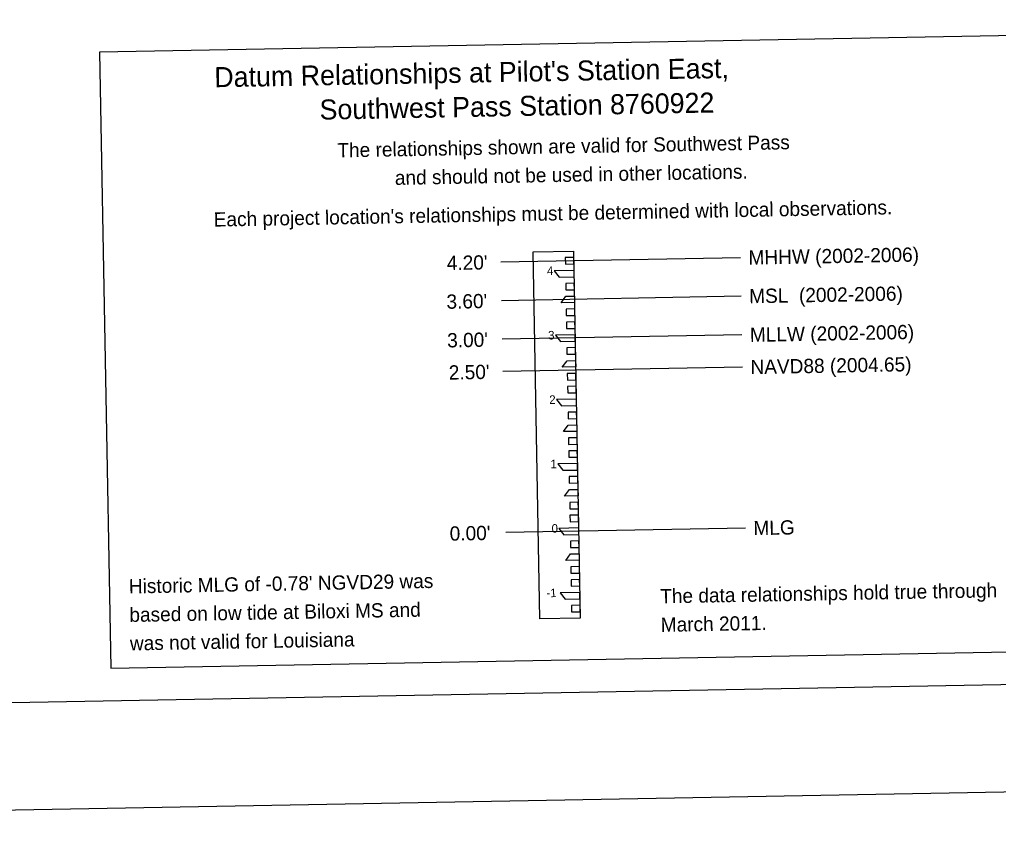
# Model space of a CAD drawing. Extents: x 3925854 to 3964121, y 224593 to 250589.
# Drawn here: x 3936067 to 3941766, y 225176 to 229943 of the extents above; entities that cross this region are included whole.
import ezdxf

# ---------------------------------------------------------------- set-up
doc = ezdxf.new("R2010")
doc.units = 0
for name, color, linetype in [('G-ANNO-NPLT', 7, 'Continuous'), ('V-ANNO-NOTE', 7, 'Continuous'), ('V-ANNO-SYMB', 7, 'Continuous')]:
    doc.layers.add(name, color=color, linetype=linetype)

msp = doc.modelspace()

# ---------------------------------------------------------------- linework, layer by layer
at = {"layer": 'G-ANNO-NPLT'}
msp.add_lwpolyline([(3926876.838, 225176.36), (3963537.445, 225842.962), (3963098.093, 250005.635), (3926437.486, 249339.033)], close=True, dxfattribs=at)
at = {"layer": 'V-ANNO-NOTE'}
for p, q in [((3940264.23, 228557.002), (3938869.243, 228531.637)), ((3940268.32, 228332.039), (3938873.334, 228306.674)), ((3940272.411, 228107.076), (3938877.424, 228081.711)), ((3940275.82, 227919.607), (3938880.833, 227894.242)), ((3940292.864, 226982.262), (3938897.877, 226956.897))]:
    msp.add_line(p, q, dxfattribs=at)
for points in [[(3936598.05, 226166.493), (3942365.934, 226271.371), (3942300.712, 229858.371), (3936532.827, 229753.493)], [(3939057.393, 228591.224), (3939293.152, 228595.511), (3939332.009, 226458.551), (3939096.249, 226454.264)], [(3939293.831, 228558.204), (3939244.066, 228557.299), (3939244.751, 228519.618), (3939294.516, 228520.523)], [(3939295.194, 228483.216), (3939180.065, 228481.123), (3939209.537, 228443.965), (3939295.879, 228445.535)], [(3939296.558, 228408.229), (3939246.793, 228407.324), (3939247.478, 228369.643), (3939297.243, 228370.548)], [(3939298.606, 228295.56), (3939220.054, 228294.132), (3939248.156, 228332.336), (3939297.921, 228333.241)], [(3939299.285, 228258.253), (3939249.52, 228257.349), (3939250.205, 228219.668), (3939299.97, 228220.573)], [(3939300.648, 228183.266), (3939250.883, 228182.361), (3939251.568, 228144.68), (3939301.333, 228145.585)], [(3939302.012, 228108.278), (3939186.882, 228106.185), (3939216.355, 228069.027), (3939302.697, 228070.597)], [(3939303.375, 228033.291), (3939253.61, 228032.386), (3939254.296, 227994.705), (3939304.06, 227995.61)], [(3939305.424, 227920.622), (3939226.872, 227919.194), (3939254.974, 227957.398), (3939304.739, 227958.303)], [(3939306.102, 227883.315), (3939256.337, 227882.411), (3939257.023, 227844.73), (3939306.787, 227845.635)], [(3939307.466, 227808.328), (3939257.701, 227807.423), (3939258.386, 227769.742), (3939308.151, 227770.647)], [(3939308.829, 227733.34), (3939193.7, 227731.247), (3939223.172, 227694.089), (3939309.514, 227695.659)], [(3939310.193, 227658.353), (3939260.428, 227657.448), (3939261.113, 227619.767), (3939310.878, 227620.672)], [(3939312.241, 227545.684), (3939233.689, 227544.256), (3939261.791, 227582.46), (3939311.556, 227583.365)], [(3939312.92, 227508.377), (3939263.155, 227507.473), (3939263.84, 227469.792), (3939313.605, 227470.697)], [(3939314.283, 227433.39), (3939264.518, 227432.485), (3939265.204, 227394.804), (3939314.968, 227395.709)], [(3939315.647, 227358.402), (3939200.517, 227356.309), (3939229.99, 227319.151), (3939316.332, 227320.721)], [(3939317.01, 227283.415), (3939267.245, 227282.51), (3939267.931, 227244.829), (3939317.695, 227245.734)], [(3939319.059, 227170.746), (3939240.507, 227169.318), (3939268.609, 227207.522), (3939318.374, 227208.427)], [(3939319.737, 227133.439), (3939269.972, 227132.534), (3939270.658, 227094.854), (3939320.422, 227095.759)], [(3939321.101, 227058.452), (3939271.336, 227057.547), (3939272.021, 227019.866), (3939321.786, 227020.771)], [(3939322.464, 226983.464), (3939207.335, 226981.371), (3939236.807, 226944.213), (3939323.149, 226945.783)], [(3939323.828, 226908.477), (3939274.063, 226907.572), (3939274.748, 226869.891), (3939324.513, 226870.796)], [(3939325.876, 226795.808), (3939247.324, 226794.38), (3939275.426, 226832.584), (3939325.191, 226833.489)], [(3939326.555, 226758.501), (3939276.79, 226757.596), (3939277.475, 226719.916), (3939327.24, 226720.821)], [(3939327.918, 226683.514), (3939278.153, 226682.609), (3939278.839, 226644.928), (3939328.603, 226645.833)], [(3939329.282, 226608.526), (3939214.152, 226606.433), (3939243.625, 226569.275), (3939329.967, 226570.845)], [(3939330.645, 226533.539), (3939280.88, 226532.634), (3939281.566, 226494.953), (3939331.33, 226495.858)]]:
    msp.add_lwpolyline(points, close=True, dxfattribs=at)
at = {"layer": 'V-ANNO-SYMB'}
msp.add_lwpolyline([(3929615.153, 225851.3), (3962692.886, 226452.755), (3962276.261, 249365.543), (3929198.528, 248764.088), (3929615.153, 225851.3)], dxfattribs=at)

# ---------------------------------------------------------------- texts
at = {"layer": 'V-ANNO-NOTE'}
for s, height, rotation, p in [("Datum Relationships at Pilot's Station East,", 116.7, 1.041707, (3937201.936, 229549.043)), ('Southwest Pass Station 8760922', 116.7, 1.041707, (3937814.695, 229360.452)), ('The relationships shown are valid for Southwest Pass', 83, 1.041699, (3937918.286, 229140.413)), ('and should not be used in other locations.', 83, 1.041699, (3938252.844, 228980.469)), ("Each project location's relationships must be determined with local observations.", 83, 1.041699, (3937198.224, 228737.768)), ('MHHW (2002-2006)', 83, 1.041707, (3940311.659, 228516.358)), ("4.20'", 83, 1.041707, (3938555.258, 228484.421)), ('4', 49.8, 1.041707, (3939138.008, 228455.454)), ('MSL  (2002-2006)', 83, 1.041707, (3940315.749, 228291.395)), ("3.60'", 83, 1.041707, (3938553.444, 228259.351)), ('3', 49.8, 1.041707, (3939144.826, 228080.516)), ('MLLW (2002-2006)', 83, 1.041707, (3940319.84, 228066.432)), ("3.00'", 83, 1.041707, (3938557.534, 228034.388)), ('NAVD88 (2004.65)', 83, 1.041707, (3940323.248, 227878.963)), ("2.50'", 83, 1.041707, (3938566.848, 227847.026)), ('2', 49.8, 1.041707, (3939151.643, 227705.578)), ('1', 49.8, 1.041707, (3939158.461, 227330.64)), ("0.00'", 83, 1.041707, (3938572.082, 226909.466)), ('0', 49.8, 1.041707, (3939165.278, 226955.702)), ('MLG', 83, 1.041707, (3940340.292, 226941.618)), ("Historic MLG of -0.78' NGVD29 was", 83, 1.041699, (3936704.19, 226602.315)), ('The data relationships hold true through ', 83, 1.041699, (3939797.762, 226544.53)), ('-1', 49.8, 1.041707, (3939135.252, 226580.094)), ('based on low tide at Biloxi MS and', 83, 1.041699, (3936707.208, 226436.343)), ('March 2011.  ', 83, 1.041699, (3939800.78, 226378.557)), ('was not valid for Louisiana', 83, 1.041699, (3936710.225, 226270.37))]:
    msp.add_text(s, height=height, rotation=rotation, dxfattribs=at).set_placement(p)

doc.saveas('drawing.dxf')
